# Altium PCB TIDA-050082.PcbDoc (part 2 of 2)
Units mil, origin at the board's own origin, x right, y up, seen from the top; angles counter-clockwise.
Board outline 3622.05 x 2047.24 mil, 6 copper layers (Top Layer, Signal Layer 1, Signal Layer 2, Signal Layer 3, Signal Layer 4, Bottom Layer), stack 61.4 mil thick; 61 components, 29 nets, 139 pads, 38 vias.
Unrouted connection lines stored in the file: 18.
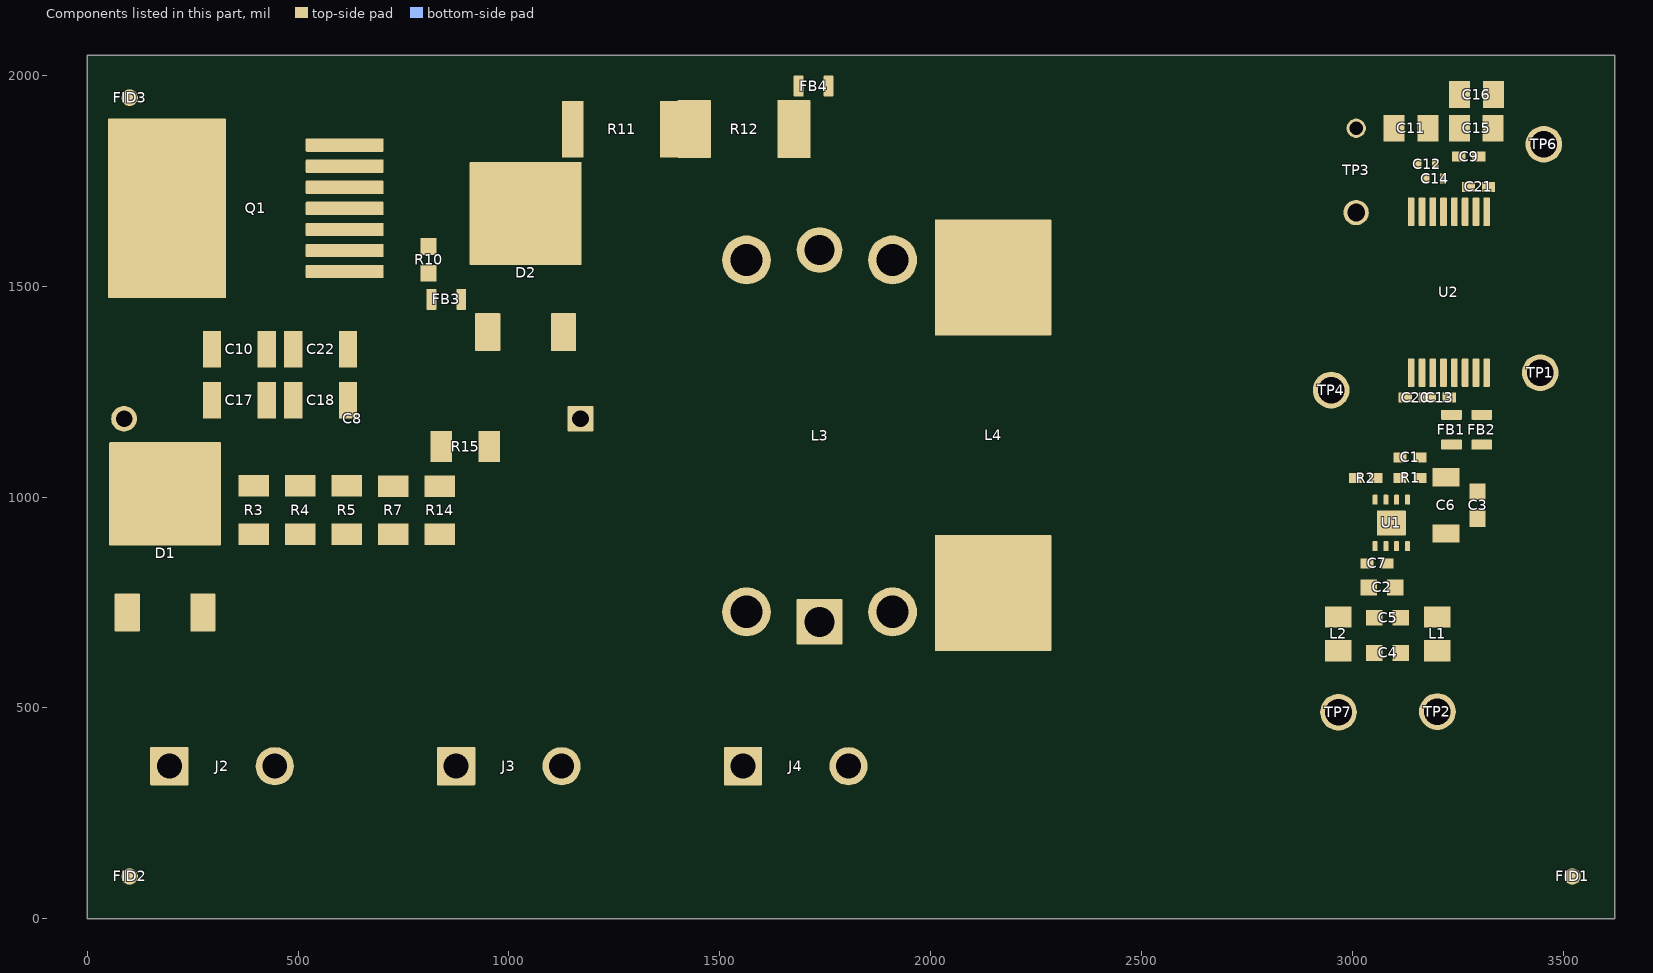
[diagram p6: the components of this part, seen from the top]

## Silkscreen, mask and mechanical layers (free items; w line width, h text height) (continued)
M10 Fab Notes:
  drawing of 189 lines, arcs and shapes, not listed
  text "DESIGN INFORMATION" at 12385.04,6394.11 h60
  text "MIN. TRACK WIDTH:" at 11740.48,6261.98 h60
  text "10" at 12836.73,6261.99 h60
  text "MIL" at 12991.48,6261.98 h60
  text "MIN. CLEARANCE:" at 11740.48,6137.86 h60
  text "0.2" at 12776.73,6137.86 h60
  text "mm" at 12991.48,6137.86 h60
  text "MIN. VIA PAD SIZE:" at 11740.48,6013.73 h60
  text "20" at 12806.73,6013.74 h60
  text "MIL" at 12991.48,6013.73 h60
  text "0.05mm (2MIL)" at 12435.48,5883.83 h60
  text "MINIMUM ANNULAR RING" at 11411.25,5875.61 h60
  text "EXTERNAL" at 13143.48,5875.61 h60
  text "PER" at 11611.25,5765.48 h60
  text "IPC-D-275 CLASS 2 LEVEL C" at 11831.25,5765.48 h60
  text "MIL, HOLES" at 13319.48,5665.01 h60
  text "+/-" at 12927.02,5656.42 h60
  text "+/-" at 13781.02,5656.42 h60
  text "REGISTRATION TOLERANCES:" at 11411.25,5655.36 h60
  text "METAL" at 12611.02,5655.36 h60
  text "5" at 13187.23,5655.36 h60
  text "3" at 14020.23,5655.36 h60
  text "MIL" at 14136.48,5655.36 h60
  text "HOLE SIZE TOLERANCE (UNLESS OTHERWISE SPECIFIED):" at 11411.25,5557.04 h60
  text "+/-" at 13781.02,5554.17 h60
  text "3" at 14020.23,5553.11 h60
  text "MIL" at 14136.48,5553.1 h60
  text "MATERIAL:" at 11336.48,5415.46 h60
  text "FR-4 High Tg" at 12322.93,5286.93 h60
  text "X" at 12178.49,5278.94 h60
  text "FR-408" at 11757.48,5274.43 h60
  text "OTHER" at 13245.48,5274.43 h60
  text "62 MIL (1.6mm) +/-10%" at 12077.59,5131.4 h60
  text "X" at 11957.49,5128.94 h60
  text "THICKNESS:" at 11411.25,5123.17 h60
  text "OTHER" at 13362.48,5123.17 h60
  text "TOLERANCE:" at 11411.25,4984.86 h60
  text "X" at 12259.49,4984.86 h60
  text "ANSI IPC-6012 TYPE 3 CLASS 2" at 12437.5,4984.86 h60
  text "OTHER +/-" at 12437.48,4840.67 h60
  text "BOW & TWIST:" at 11411.25,4695.48 h60
  text "X" at 12259.49,4695.48 h60
  text "ANSI IPC-6012 TYPE 3 CLASS 2" at 12437.5,4695.48 h60
  text "OTHER +/-" at 12437.48,4548.79 h60
  text "DRILLING:" at 11336.48,4418.17 h60
  text "NC_DRILL FILES" at 13097.48,4312.98 h60
  text "REFERENCE:" at 11411.25,4309.04 h60
  text "X" at 12068.49,4308.94 h60
  text "AS SHOWN" at 12246.48,4309.04 h60
  text "X" at 12969.49,4309.04 h60
  text "OTHER" at 13395.48,4166.79 h60
  text "PTH COPPER THICKNESS:" at 11410.93,4163.26 h60
  text "X" at 12550.17,4163.26 h60
  text "20-30 um" at 12678.16,4163.26 h60
  text "BOARD FINISH:" at 11336.48,4015.66 h60
  text "SILKSCREEN:" at 11491.7,3905.54 h60
  text "X" at 12449.49,3905.54 h60
  text "TOP" at 12566.48,3905.54 h60
  text "BOTTOM" at 13077.48,3905.54 h60
  text "SILKSCREEN COLOR:" at 11491.7,3750.35 h60
  text "X" at 12448.49,3750.35 h60
  text "WHITE" at 12566.48,3750.35 h60
  text "OTHER" at 13077.48,3750.35 h60
  text "X" at 12579.49,3606.9 h60
  text "GREEN" at 12697.48,3606.9 h60
  text "OTHER" at 13315.48,3606.9 h60
  text "SOLDER RESIST COLOR:" at 11491.7,3600.03 h60
  text "X" at 12579.49,3452.65 h60
  text "MATTE" at 12697.48,3452.65 h60
  text "SEMI-GLOSS" at 13315.02,3452.01 h60
  text "IMMERSION GOLD (ENIG)" at 12397.48,3279.88 h60
  text "ENEPIG" at 13735.02,3272.65 h60
  text "SURFACE FINISH:" at 11336.48,3271.65 h60
  text "X" at 12219.49,3271.65 h60
  text "IMM. TIN/SILVER OR EQUIV" at 11666.02,3134.34 h60
  text "OTHER" at 13097.48,3130.4 h60
  text "ARRAY/PANEL:" at 11336.48,2975.02 h60
  text "CUT AND TRIM PER M1 BOARD OUTLINE" at 12397.48,2966.8 h60
  text "N.C. ROUTE" at 12397.48,2830.84 h60
  text "X" at 13085.49,2830.84 h60
  text "V. SCORE" at 13263.48,2830.84 h60
  text "CERTIFICATION:" at 11336.48,2701.71 h60
  text "MATERIALS AND WORKMANSHIP FOR ALL PCBS" at 12061.48,2701.71 h60
  text "TO MEET OR EXCEED THE REQUIREMENTS OF:" at 12061.48,2607.65 h60
  text "X" at 11698.99,2479.02 h60
  text "ANSI IPC-A-600F CLASS ->" at 11826.99,2479.02 h60
  text "X" at 13474.99,2479.02 h60
  text "2" at 13584.99,2479.02 h60
  text "1" at 13269.99,2477.52 h60
  text "3" at 13938.99,2477.52 h60
  text "X" at 12510.99,2331.33 h60
  text "RoHS" at 12638.99,2331.33 h60
  text "OTHER" at 13283.39,2331.33 h60
  text "PER ORDER" at 13680.45,2331.33 h60
  text "ALL BOARDS MUST MEET OR EXCEED UL94-V0 REQUIREMENTS." at 11364.02,2177.5 h60
  text "PCB MUST BEAR THE UL94V-0 UL REGISTERED MATERIAL ID NUMBER" at 11364.02,2061.44 h60
  text "ADDITIONAL REQUIREMENTS:" at 11336.48,1892.02 h60
  text "MICROSECTION:" at 11411.25,1784.89 h60
  text "YES" at 12316.99,1784.89 h60
  text "REQUIRED" at 13178.48,1640.56 h60
  text "BARE BOARD ELEC. TEST:" at 11411.25,1637.7 h60
  text "NONE" at 12716.99,1637.7 h60
  text "X" at 13060.49,1637.7 h60
  text "PER ORDER" at 13770.48,1637.7 h60
  text "XX MIL VIAS REQUIRE NON-CONDUCTIVE FILL AND PLANARIZE" at 11579.4,1432.75 h59
  text "XX MIL VIAS REQUIRE CONDUCTIVE FILL AND PLANARIZE" at 11587.4,1328.78 h60
  text "X" at 11475.57,1327.44 h60
  text "OUTER XX MIL TRACES REQUIRE 50 OHM SINGLE-ENDED IMPEDANCE" at 11586.42,1165.39 h58
  text "LAYER 2 & 3 (INNER LAYERS) XX MIL WIDE, XX MIL SPACE / TRACES REQUIRE 100 OHM DIFFERENTIAL IMPEDANCE" at 11578.42,929.68 h60
  text ".Layer_Name" at 580.02,-820.56 h60
M11 Gerber Information:
  lines w10: -288.98,-892.23 6311.02,-892.23 ; -288.98,-688.9 6313.02,-688.9 ; -288.98,-485.56 -288.98,-1095.56 3716.02,-1095.56 6313.02,-1095.56 6313.02,-485.56 -288.48,-485.56 -288.48,-1095.56 1287.02,-1095.56 ; 2176.02,-1095.56 2176.02,-485.56 ; 3443.02,-688.9 3443.02,-485.56 ; 4283.02,-688.9 4283.02,-485.56 ; 4905.02,-1102.06 4905.02,-899.23
  text "ALL ARTWORK VIEWED FROM TOP SIDE" at -225.48,-617.73 h60
  text "BOARD #:" at 2251.02,-617.73 h60
  text ".PRJ_Number" at 2796.52,-617.73 h60
  text "REV:" at 3641.02,-617.73 h60
  text ".PCB_Rev" at 3932.52,-617.73 h60
  text "SVN REV:" at 4479.02,-617.73 h60
  text ".VersionControl_RevNumber" at 4985.02,-617.73 h60
  text "LAYER NAME =" at -225.48,-820.56 h60
  text "TID #:" at 2251.02,-821.06 h60
  text ".TID" at 2796.52,-821.06 h60
  text "PLOT NAME =" at -225.48,-1026.4 h60
  text ".plot_File_Name" at 580.02,-1026.4 h60
  text "GENERATED    :" at 2253.02,-1026.4 h60
  text ".Print_Date" at 3122.52,-1026.4 h60
  text ".Print_Time" at 3851.52,-1026.4 h60
  text "TEXAS INSTRUMENTS" at 5116.02,-1026.4 h60
M12 Stackup:
  drawing of 399 lines, arcs and shapes, not listed
  text "Layer" at 6739.65,7559.01 h60
  text "Name" at 7149.56,7559.01 h60
  text "Material" at 8089.3,7559.01 h60
  text "Thickness" at 8949.07,7559.01 h60
  text "Constant" at 9598.9,7559.01 h60
  text "Board Layer Stack" at 10168.76,7559.01 h60
  text "Top Overlay" at 7149.56,7439.01 h60
  text "Top Solder" at 7149.56,7319.01 h60
  text "Solder Resist" at 8089.3,7319.01 h60
  text "0.50mil" at 8949.07,7319.01 h60
  text "3.5" at 9598.9,7319.01 h60
  text "1" at 6739.65,7199.01 h60
  text "Top Layer" at 7149.56,7199.01 h60
  text "2.80mil" at 8949.07,7199.01 h60
  text "Dielectric 1" at 7149.56,7079.01 h60
  text "FR-4 High Tg" at 8089.3,7079.01 h60
  text "7.00mil" at 8949.07,7079.01 h60
  text "4.2" at 9598.9,7079.01 h60
  text "2" at 6739.65,6959.01 h60
  text "Signal Layer 1" at 7149.56,6959.01 h60
  text "1.40mil" at 8949.07,6959.01 h60
  text "Dielectric 2" at 7149.56,6839.01 h60
  text "FR-4 High Tg" at 8089.3,6839.01 h60
  text "14.00mil" at 8949.07,6839.01 h60
  text "4.2" at 9598.9,6839.01 h60
  text "3" at 6739.65,6719.01 h60
  text "Signal Layer 2" at 7149.56,6719.01 h60
  text "1.40mil" at 8949.07,6719.01 h60
  text "Dielectric 4" at 7149.56,6599.01 h60
  text "FR-4 High Tg" at 8089.3,6599.01 h60
  text "8.20mil" at 8949.07,6599.01 h60
  text "4.2" at 9598.9,6599.01 h60
  text "4" at 6739.65,6479.01 h60
  text "Signal Layer 3" at 7149.56,6479.01 h60
  text "1.40mil" at 8949.07,6479.01 h60
  text "Dielectric 5" at 7149.56,6359.01 h60
  text "FR-4 High Tg" at 8089.3,6359.01 h60
  text "14.00mil" at 8949.07,6359.01 h60
  text "4.2" at 9598.9,6359.01 h60
  text "5" at 6739.65,6239.01 h60
  text "Signal Layer 4" at 7149.56,6239.01 h60
  text "1.40mil" at 8949.07,6239.01 h60
  text "Dielectric 3" at 7149.56,6119.01 h60
  text "FR-4 High Tg" at 8089.3,6119.01 h60
  text "7.00mil" at 8949.07,6119.01 h60
  text "4.2" at 9598.9,6119.01 h60
  text "6" at 6739.65,5999.01 h60
  text "Bottom Layer" at 7149.56,5999.01 h60
  text "2.80mil" at 8949.07,5999.01 h60
  text "Bottom Solder" at 7149.56,5879.01 h60
  text "Solder Resist" at 8089.3,5879.01 h60
  text "0.50mil" at 8949.07,5879.01 h60
  text "3.5" at 9598.9,5879.01 h60
  text "Bottom Overlay" at 7149.56,5759.01 h60
  text ".Layer_Name" at 580.02,-820.56 h60
M13 Component Bodies Top:
  text ".Layer_Name" at 580.02,-820.56 h60
M14 Component Bodies Bottom:
  text ".Layer_Name" at 580.02,-820.56 h60
M15 Courtyards Top:
  text ".Layer_Name" at 580.02,-820.56 h60
M16 Courtyards Bottom:
  text ".Layer_Name" at 580.02,-820.56 h60
Drill Drawing:
  circle w10: c4686.35,1275.7 r16.58
  circle w10: c4686.35,1275.7 r27.63
  circle w10: c4686.35,529.78 r27.63
  lines w10: 4658.72,681.73 4713.98,681.73 4686.35,626.48 4658.72,681.73 ; 4658.72,750.8 4713.98,750.8 4713.98,806.05 4658.72,806.05 4658.72,750.8 ; 4658.72,888.93 4672.54,888.93 4672.54,875.12 4700.16,875.12 4700.16,888.93 4713.98,888.93 4713.98,916.56 4700.16,916.56 4700.16,930.37 4672.54,930.37 4672.54,916.56 4658.72,916.56 4658.72,888.93 ; 4658.72,1054.69 4713.98,1054.69 4686.35,999.44 4658.72,1054.69 ; 4658.72,1137.57 4672.54,1137.57 4686.35,1123.76 4700.16,1137.57 4713.98,1137.57 4700.16,1151.38 4713.98,1165.2 4700.16,1165.2 4686.35,1179.01 4672.54,1165.2 4658.72,1165.2 4672.54,1151.38 4658.72,1137.57 ; 4658.72,1372.4 4686.35,1386.21 4713.98,1372.4 4700.16,1400.02 4713.98,1427.65 4686.35,1413.84 4658.72,1427.65 4672.54,1400.02 4658.72,1372.4 ; 4669.77,761.85 4702.93,761.85 4702.93,795 4669.77,795 4669.77,761.85 ; 4669.77,1043.64 4702.93,1043.64 4686.35,1010.49 4669.77,1043.64
  lines w12: 4608.63,464.86 7840.12,464.86 ; 4608.63,1459.42 7840.12,1459.42 ; 4946.5,340.54 4946.5,1583.74 ; 5278.5,340.54 5278.5,1583.74 ; 5915.06,340.54 5915.06,1583.74 ; 6174.2,340.54 6174.2,1583.74 ; 6549.36,340.54 6549.36,1583.74 ; 7273.69,340.54 7273.69,1583.74 ; 4608.63,340.54 7840.12,340.54 7840.12,1583.74 4608.63,1583.74 4608.63,340.54
  text "Symbol" at 4683.23,1496.72 h72
  text "Quantity" at 4983.79,1496.72 h72
  text "Finished Hole Size" at 5315.79,1496.72 h72
  text "Plated" at 5952.36,1496.72 h72
  text "Hole Type" at 6211.5,1496.72 h72
  text "Drill Layer Pair" at 6586.65,1496.72 h72
  text "Hole Tolerance" at 7310.98,1496.72 h72
  text "38" at 4983.79,1372.4 h60
  text "12.00mil (0.305mm)" at 5315.79,1372.4 h60
  text "PTH" at 5952.36,1372.4 h60
  text "Round" at 6211.5,1372.4 h60
  text "Top Layer - Bottom Layer" at 6586.65,1372.4 h60
  text "1" at 4983.79,1248.08 h60
  text "32.00mil (0.813mm)" at 5315.79,1248.08 h60
  text "PTH" at 5952.36,1248.08 h60
  text "Round" at 6211.5,1248.08 h60
  text "Top Layer - Bottom Layer" at 6586.65,1248.08 h60
  text "2" at 4983.79,1123.76 h60
  text "39.37mil (1.000mm)" at 5315.79,1123.76 h60
  text "PTH" at 5952.36,1123.76 h60
  text "Round" at 6211.5,1123.76 h60
  text "Top Layer - Bottom Layer" at 6586.65,1123.76 h60
  text "1" at 4983.79,999.44 h60
  text "42.00mil (1.067mm)" at 5315.79,999.44 h60
  text "PTH" at 5952.36,999.44 h60
  text "Round" at 6211.5,999.44 h60
  text "Top Layer - Bottom Layer" at 6586.65,999.44 h60
  text "6" at 4983.79,875.12 h60
  text "59.06mil (1.500mm)" at 5315.79,875.12 h60
  text "PTH" at 5952.36,875.12 h60
  text "Round" at 6211.5,875.12 h60
  text "Top Layer - Bottom Layer" at 6586.65,875.12 h60
  text "5" at 4983.79,750.8 h60
  text "63.00mil (1.600mm)" at 5315.79,750.8 h60
  text "PTH" at 5952.36,750.8 h60
  text "Round" at 6211.5,750.8 h60
  text "Top Layer - Bottom Layer" at 6586.65,750.8 h60
  text "2" at 4983.79,626.48 h60
  text "71.00mil (1.803mm)" at 5315.79,626.48 h60
  text "PTH" at 5952.36,626.48 h60
  text "Round" at 6211.5,626.48 h60
  text "Top Layer - Bottom Layer" at 6586.65,626.48 h60
  text "4" at 4983.79,502.16 h60
  text "76.51mil (1.943mm)" at 5315.79,502.16 h60
  text "PTH" at 5952.36,502.16 h60
  text "Round" at 6211.5,502.16 h60
  text "Top Layer - Bottom Layer" at 6586.65,502.16 h60
  text "59 Total" at 4983.79,377.84 h60
  text ".Layer_Name" at 580.02,-820.56 h60
Mechanical 17:
  text ".Layer_Name" at 580.02,-820.56 h60
Mechanical 18:
  text ".Layer_Name" at 580.02,-820.56 h60
Mechanical 19:
  text ".Layer_Name" at 580.02,-820.56 h60

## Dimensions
0,0 to 3622.05,0 on M2 Board Dimensions
0,0 to 0,2047.24 on M2 Board Dimensions
3.02,-362.06 to 1003.02,-362.06 on M2 Board Dimensions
